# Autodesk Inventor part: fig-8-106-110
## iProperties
Created: 2007-06
Part Number: fig-8-106-110
Document SubType Name: Modeling
Designer: Administrator
Density: 1 g/cm^3
Author: Administrator
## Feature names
1. Extrusion1
